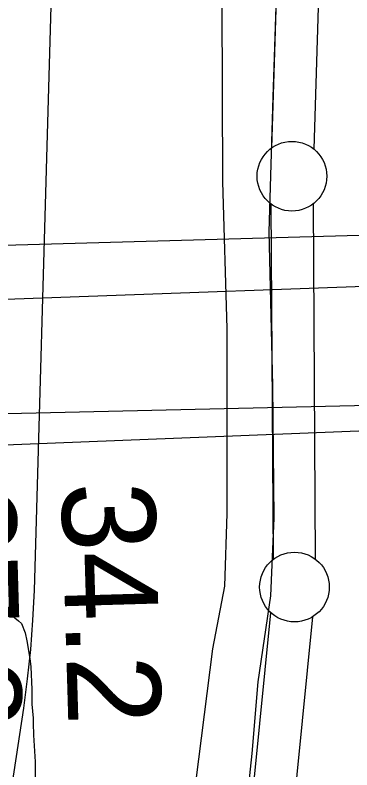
# Model space of a CAD drawing. Extents: x 3297716 to 3335574, y 688621 to 713991.
# Drawn here: x 3325608 to 3325850, y 706063 to 706604 of the extents above; entities that cross this region are included whole.
import ezdxf

# ---------------------------------------------------------------- set-up
doc = ezdxf.new("R2010")
doc.units = 0
for name, color, linetype in [('V-CHAN-DOCK', 7, 'Continuous'), ('V-FLOD-BASE', 7, 'Continuous'), ('V-LEVE-TOET', 7, 'Continuous'), ('V-RIVR-RANG', 7, 'Continuous'), ('V-SITE-VEGE', 7, 'Continuous'), ('V-SURV-LINE', 7, 'Continuous'), ('V-TOPO-MINR', 7, 'Continuous')]:
    doc.layers.add(name, color=color, linetype=linetype)

msp = doc.modelspace()

# ---------------------------------------------------------------- linework, layer by layer
at = {"layer": 'V-CHAN-DOCK'}
for points in [[(3325863.34, 706446.26), (3325336.53, 706431.48), (3325337.12, 706444.45), (3325317.03, 706443.7), (3325320.17, 706465.1), (3325294.89, 706464.99), (3325293.05, 706442.95), (3325276.21, 706442.22), (3325287.78, 706184.34), (3325341.56, 706186.54), (3325340.45, 706285.69), (3325884.73, 706307.03)], [(3325882.71, 706324.52), (3325529.3, 706316.54), (3325528.36, 706397.64), (3326003.86, 706414.93)]]:
    msp.add_lwpolyline(points, dxfattribs=at)
at = {"layer": 'V-FLOD-BASE'}
msp.add_lwpolyline([(3325720.28, 707381.54), (3325718.26, 707259.69), (3325715.42, 707175.43), (3325747, 707073.83), (3325759.48, 707037.59), (3325774.05, 706970.91), (3325783.94, 706934.66), (3325794.95, 706910.95), (3325796.48, 706886.12), (3325797.87, 706866.68), (3325803.17, 706841.43), (3325798.56, 706718.92), (3325792.89, 706545.21), (3325790.11, 706448.64), (3325792.57, 706338.47), (3325793.66, 706243.21), (3325791.33, 706187.47), (3325782.16, 706125.93), (3325777.73, 706074.48), (3325773.03, 706029.52), (3325770.1, 705999.99), (3325752.93, 705821.59), (3325746.61, 705686.4), (3325740.27, 705596.13)], dxfattribs=at)
at = {"layer": 'V-LEVE-TOET'}
msp.add_lwpolyline([(3325710.15, 705781.42), (3325721.66, 705927.19), (3325749.77, 706149.63), (3325758.37, 706194.4), (3325760.16, 706246.6), (3325760.21, 706379.44), (3325757.01, 706484.48), (3325756.41, 706613.25)], dxfattribs=at)
at = {"layer": 'V-SITE-VEGE'}
msp.add_lwpolyline([(3325605.17, 706173.88), (3325610.31, 706169.69), (3325612.43, 706167.59), (3325615.17, 706160.98), (3325616.4, 706155.26), (3325618.56, 706142.63), (3325619.19, 706136.61), (3325619.86, 706120.35), (3325619.91, 706109.81), (3325620.85, 706099.88), (3325620.87, 706096.27), (3325621.21, 706087.54), (3325622.19, 706068.57), (3325622.25, 706055.02)], dxfattribs=at)
at = {"layer": 'V-SURV-LINE'}
for points in [[(3325792.26, 706509.02), (3325801.94, 706822.32)], [(3325831.92, 706821.37), (3325822.24, 706508.08)], [(3325793.3, 706213.71), (3325791.75, 706468.51)], [(3325821.75, 706468.69), (3325823.3, 706213.9)], [(3325720.24, 705458.31), (3325791.52, 706175.45)], [(3325821.37, 706172.47), (3325750.1, 705455.33)]]:
    msp.add_lwpolyline(points, dxfattribs=at)
for centre in [(3325806.63, 706488.57), (3325808.42, 706193.84)]:
    msp.add_circle(centre, 25, dxfattribs=at)
at = {"layer": 'V-TOPO-MINR'}
msp.add_lwpolyline([(3325508.28, 705533.43), (3325522.18, 705612.39), (3325530.69, 705658.6), (3325539.67, 705704.71), (3325549.37, 705750.67), (3325559.55, 705796.54), (3325569.57, 705842.43), (3325578.9, 705888.46), (3325587.2, 705934.68), (3325594.82, 705981.03), (3325614.07, 706106.96), (3325616.88, 706127.97), (3325619.18, 706149.03), (3325620.7, 706170.16), (3325621.7, 706191.33), (3325642.43, 706912.91)], dxfattribs=at)

# ---------------------------------------------------------------- texts
at = {"layer": 'V-RIVR-RANG'}
for s, p in [('27.8', (3325541.1, 706265.23)), ('34.2', (3325641.05, 706268.41))]:
    msp.add_text(s, height=67, rotation=271.6783, dxfattribs=at).set_placement(p)

doc.saveas('drawing.dxf')
